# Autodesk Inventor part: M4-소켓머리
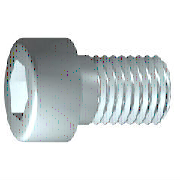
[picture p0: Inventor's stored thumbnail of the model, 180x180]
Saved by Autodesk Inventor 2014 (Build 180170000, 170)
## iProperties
IsCustomPart: 0
Created: 2009-02
Part Number: M4-소켓머리
Material: 강, 연강
Description: 6각머리 태핑 나사
Document SubType Name: Modeling
Standard: KS B 1003
Designer: 한국산업디자인학원 [http://gmhk.co.kr]
Standards Organization: KS
Language: ko-KR
Size Designation: M 4 x 12
Categories: <MemberInstance><Categories><Category DisplayName="조임쇠" InternalName="e4da775c-781d-43d5-af7c-5136215cf5a6" Mnemonic="FSTN"><Category DisplayName="볼트" InternalN
Density: 1 g/cm^3
Appearance: _시험-금속-강(연마)
Author: pww
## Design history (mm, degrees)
sketch "스케치1"
  geometry: L1 (-1, 0)-(12, 0); L2 (12, 0)-(12, 2); L3 (12, 2)-(1.75, 2); L4 (1.75, 2)-(1.32, 2); L5 (1.32, 2)-(0, 2); L6 (0, 2)-(0, 3.5); L7 (0, 3.5)-(-4, 3.5); L8 (-4, 3.5)-(-4, 1.732); L9 (-4, 1.732)-(-2, 1.732); L10 (-2, 1.732)-(-1, 0); L11 (-7.2, 0)-(15.2, 0) reference; L12 (0, -0.7)-(0, 4.2) reference; L13 (1.75, 2)-(0, 2)
  constraints: 22 end point, 6 parallel, 2 collinear, 2 perpendicular, 1 horizontal, 1 point on line
  dimensions: "d1" = 10.25 distance from line of L3.end L2 (= GEL); "d2" = 0.42952 distance of L4.end L3.end (computed from GAL); "d3" = 4 distance between parallel lines of L8 L6 (= KOH); "d4" = 2 distance of L8.end L9.end (= INTI); "d5" = 60 deg angle of L10 L1; "d6" = 4 diameter of L3 L1 (= GD); "d7" = 4 diameter of L5 L1 (= BDM); "d8" = 3.4641 diameter of L9 L1 (= 1.1547 x SW); "d9" = 7 diameter of L7 L1 (= KOD); "d26" = 12 distance between parallel lines of L12 L2 (= NLG)
revolve "본체" sketch "스케치1" stored, may be unused: angle "d10" = 90 deg
sketch "스케치2"
  geometry: L1 (0, -4.9)-(0, 4.9) reference; L2 (-4.9, 0)-(4.9, 0) reference; L3 (1.732, 0)-(0.866, -1.5); L4 (0.866, -1.5)-(-0.866, -1.5); L5 (-0.866, -1.5)-(-1.732, 0); L6 (-1.732, 0)-(-0.866, 1.5); L7 (-0.866, 1.5)-(0.866, 1.5); L8 (0.866, 1.5)-(1.732, 0); 2 further points
  constraints: 12 end point, 1 coincident, 1 horizontal alignment, 1 point on line, 12 other
extrude "슬롯" join sketch "스케치2" stored distance "d11" = 10; taper "d12" = 0 deg
workplane "Work Plane1"
fillet "Fillet2" dims "d30" = 0.1 (= R)
body "Solid1"
fillet "모깎기1" dims "d17" = 0.4 (= RR)
feature "스레드" dims "d13" = 10.25 (= GEL), "d14" = 0
chamfer "모따기1" distance "d15" = 0.42941 (= -0.5 x SPD + 0.5 x GD); stored, may be unused: second distance "d16" = 0.42941 (= GUL), angle "d27" = 45 deg
other parameters: "GD" = 4 (= NND) [user parameter; used in 2 equation terms], "NLG" = 12 [user parameter; used in 1 equation term], "GEL" = 10.25 [user parameter; used in 2 equation terms], "KOD" = 7 [user parameter; used in 1 equation term], "KOH" = 4 [user parameter; used in 1 equation term], "INTI" = 2 [user parameter; used in 1 equation term], "GAL" = 0.42941 (= 0.61345 x PTC) [user parameter; used in 1 equation term], "GUL" = 0.42941 (= 0.61345 x PTC) [user parameter; used in 1 equation term], "BDM" = 4 (= NND) [user parameter; used in 1 equation term], "SW" = 3 [user parameter; used in 2 equation terms], "RR" = 0.4 [user parameter; used in 1 equation term], "SPD" = 3.14117 (= NND - 1.2269 x PTC) [user parameter; used in 1 equation term], "d19" = 0, "d28" = 0, "d29" = 0, "R" = 0.1 [user parameter; used in 1 equation term], "PHH" = 0.2 [user parameter], "GD1" = 3.14117 (= THREADDIA - 1.2269 x PTC) [user parameter], "THREADDIA" = 4 [user parameter; used in 1 equation term], "FAWI" = 45 deg [user parameter], "TPU" = 14.28571 (computed from PTC) [user parameter], "PTC" = 0.7 [user parameter; used in 5 equation terms], "NND" = 4 [user parameter; used in 3 equation terms], "TOA" = 30 deg [user parameter], "E0" = 3.465 (= 1.155 x SW) [user parameter]
